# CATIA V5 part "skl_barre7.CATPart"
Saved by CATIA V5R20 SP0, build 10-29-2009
Part number: skl_barre7
Publications: "Barre_71", "Barre_72", "Axe_Pivot_b7b9", "Axe_Pivot_b7b11", "Axe_Pivot_b7b8"
Bounding box of the stored display mesh (mm): x 0 to 0, y -170 to 170, z 0 to 20
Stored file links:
  C:\Users\Matthieu\Desktop\IFMA\Cours 2A\Thinkmotion\skl_barre7.CATPart
  C:\Users\Matthieu\Desktop\IFMA\Cours 2A\Thinkmotion\skl_IAO_bis.CATProduct
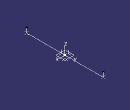
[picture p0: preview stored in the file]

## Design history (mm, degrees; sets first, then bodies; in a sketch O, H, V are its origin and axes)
AxisSystem1: origin (0, 0, 0), X (1, 0, 0), Y (0, 1, 0), Z (0, 0, 1)
Set1
  Point1 "Point.L": linked copy from another document
  Point2 "Point.A": linked copy from another document
  Point3 "Point.N": linked copy from another document
  Plane1 "Plan_Ref": linked copy from another document
Body1 (main body)
  Line1 "Barre_71": type PtPt, FirstPoint Point1, SecondPoint Point2
  Line2 "Barre_72": type PtPt, FirstPoint Point2, SecondPoint Point3
  Line3 "Axe_Pivot_b7b9": type Normal, RefPoint Point1, RefSkin Plane1, Start 0, End 20
  Line4 "Axe_Pivot_b7b11": type Normal, RefPoint Point2, RefSkin Plane1, Start 0, End 20
  Line5 "Axe_Pivot_b7b8": type Normal, RefPoint Point3, RefSkin Plane1, Start 0, End 20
